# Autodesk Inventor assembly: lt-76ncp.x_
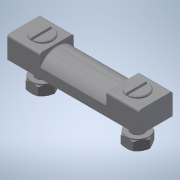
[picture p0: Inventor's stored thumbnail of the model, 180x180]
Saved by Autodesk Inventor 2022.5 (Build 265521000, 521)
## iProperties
Created: 2021-11
Part Number: lt-76ncp.x_
Material: 一般
Document SubType Name: Assembly
Designer: ImaoCorp
Sending System: SOLIDWORKS 2019-2019304
MC: AMD64
MC_MODEL: Intel64 Family 6 Model 60 Stepping 3, GenuineIntel
OS: Windows_NT
FRU: Parasolid Version 31.0, build 290,  9- 1-2019
FORMAT: text
GUISE: transmit
KEY: lt-76ncp
FILE: lt-76ncp.x_t
DATE: Mon Nov 29 13:56:33 2021
Author: ImaoCorp
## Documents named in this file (4)
- X:\14_SW2022-Inv2022\00_全2023-1023新製品(TCC)まで\l\lt-76ncp\LT-76NCP.iam
- X:\14_SW2022-Inv2022\00_全2023-1023新製品(TCC)まで\l\lt-76ncp\lt-76ncp_01.ipt
- X:\14_SW2022-Inv2022\00_全2023-1023新製品(TCC)まで\l\lt-76ncp\lt-76ncp_02.ipt
- X:\14_SW2022-Inv2022\00_全2023-1023新製品(TCC)まで\l\lt-76ncp\lt-76ncp_03.ipt
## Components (3 placed, 3 different names)
1. lt-76ncp_01
2. lt-76ncp_02
3. lt-76ncp_03
